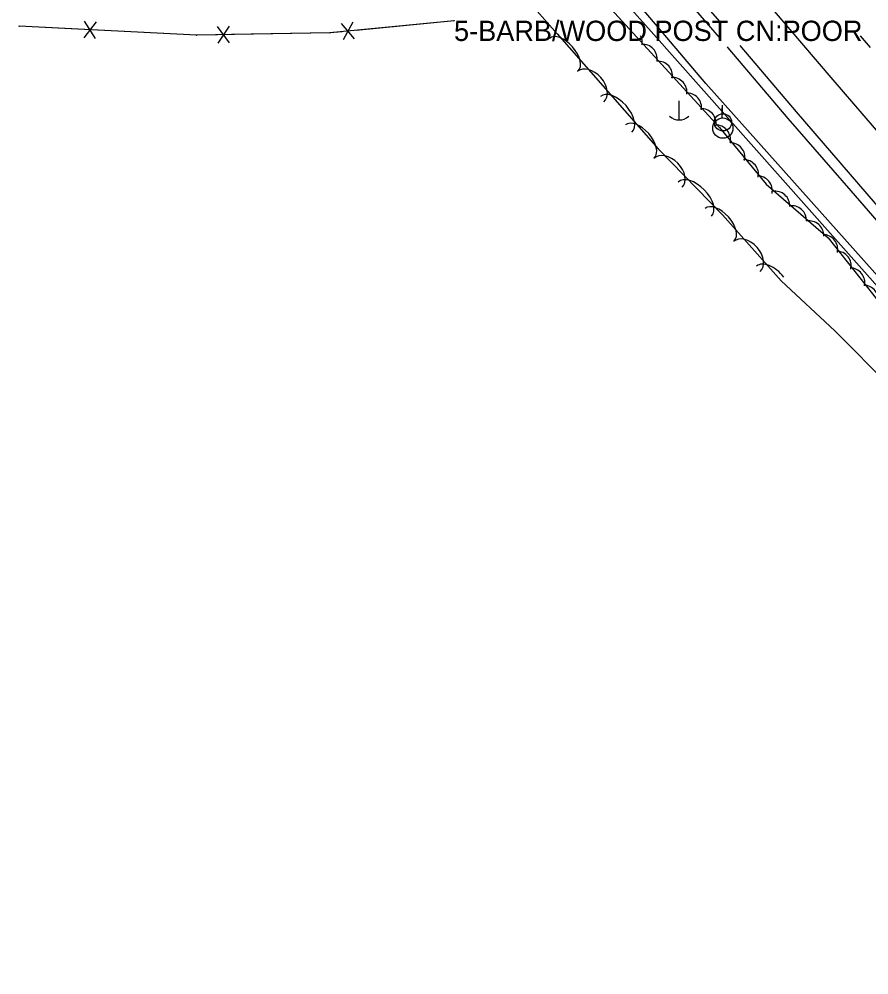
# Model space of a CAD drawing. Extents: x 954793 to 988390, y 1867850 to 1924428.
# Drawn here: x 965332 to 965541.5, y 1898519 to 1898754.5 of the extents above; entities that cross this region are included whole.
import ezdxf

# ---------------------------------------------------------------- set-up
doc = ezdxf.new("R2010")
doc.units = 0
for name, color, linetype in [('S_DITCHLINE', 7, 'Continuous'), ('S_EDGE_PAVEMENT', 7, 'Continuous'), ('S_FENCE', 7, 'Continuous'), ('S_FENCE_ANNOT', 7, 'Continuous'), ('S_MSC_PT_SYM', 7, 'Continuous'), ('S_PAVEMENT_CROWN', 7, 'Continuous'), ('S_SHOULDER', 7, 'Continuous'), ('S_TREE', 7, 'Continuous'), ('S_UTILITY_POLE', 7, 'Continuous')]:
    doc.layers.add(name, color=color, linetype=linetype)

msp = doc.modelspace()

# ---------------------------------------------------------------- linework, layer by layer
at = {"layer": 'S_DITCHLINE'}
for points in [[(965553.26, 1898680.48), (965540.28, 1898695.02), (965527.3, 1898709.56), (965514.32, 1898724.1), (965501.34, 1898738.65), (965489.36, 1898752.73), (965477.38, 1898766.82)], [(965552.07, 1898679.14), (965539.1, 1898693.76), (965526.12, 1898708.39), (965513.15, 1898723.02), (965500.18, 1898737.65), (965487.84, 1898751.51), (965475.51, 1898765.38)]]:
    msp.add_lwpolyline(points, dxfattribs=at)
at = {"layer": 'S_EDGE_PAVEMENT'}
for points in [[(965504.83, 1898753.86), (965499.61, 1898759.99)], [(965541.89, 1898747.52), (965539.42, 1898750.42)], [(965554.4, 1898696.05), (965539.02, 1898713.89), (965523.65, 1898731.73), (965509.77, 1898748.04)]]:
    msp.add_lwpolyline(points, dxfattribs=at)
at = {"layer": 'S_FENCE'}
for p, q in [((965375.73, 1898750.6), (965332.09, 1898752.81)), ((965351.04, 1898753.9), (965347.97, 1898749.95)), ((965350.83, 1898749.81), (965348.17, 1898754.04)), ((965383.86, 1898748.68), (965380.92, 1898752.73)), ((965383.79, 1898752.78), (965380.99, 1898748.63)), ((965439.24, 1898754.16), (965408.64, 1898751.14)), ((965414.74, 1898749.69), (965411.48, 1898753.48)), ((965414.34, 1898753.76), (965411.88, 1898749.41)), ((965408.64, 1898751.14), (965375.73, 1898750.6))]:
    msp.add_line(p, q, dxfattribs=at)
for points in [[(965348.07, 1898752), (965332.09, 1898752.81)], [(965439.24, 1898754.16), (965415.1, 1898751.78)], [(965375.73, 1898750.6), (965351.5, 1898751.82)], [(965380.96, 1898750.68), (965375.73, 1898750.6)], [(965408.64, 1898751.14), (965384.39, 1898750.74)], [(965411.68, 1898751.44), (965408.64, 1898751.14)]]:
    msp.add_lwpolyline(points, dxfattribs=at)
at = {"layer": 'S_MSC_PT_SYM'}
for points in [[(965332.09, 1898752.81), (965332.09, 1898752.86), (965332.09, 1898752.81), (965332.04, 1898752.81), (965332.09, 1898752.81), (965332.09, 1898752.76), (965332.09, 1898752.81), (965332.14, 1898752.81)], [(965439.24, 1898754.16), (965439.24, 1898754.21), (965439.24, 1898754.16), (965439.19, 1898754.16), (965439.24, 1898754.16), (965439.24, 1898754.11), (965439.24, 1898754.16), (965439.29, 1898754.16)], [(965375.73, 1898750.6), (965375.73, 1898750.65), (965375.73, 1898750.6), (965375.68, 1898750.6), (965375.73, 1898750.6), (965375.73, 1898750.55), (965375.73, 1898750.6), (965375.78, 1898750.6)], [(965408.64, 1898751.14), (965408.64, 1898751.19), (965408.64, 1898751.14), (965408.59, 1898751.14), (965408.64, 1898751.14), (965408.64, 1898751.09), (965408.64, 1898751.14), (965408.69, 1898751.14)]]:
    msp.add_lwpolyline(points, dxfattribs=at)
at = {"layer": 'S_PAVEMENT_CROWN'}
msp.add_lwpolyline([(965548.02, 1898721.84), (965532.67, 1898739.61), (965517.73, 1898757.07)], dxfattribs=at)
at = {"layer": 'S_SHOULDER'}
for points in [[(965504.65, 1898750.01), (965496.23, 1898759.91)], [(965552.61, 1898694.39), (965537.13, 1898712.22), (965521.64, 1898730.04), (965506.79, 1898747.5), (965506.63, 1898747.68)]]:
    msp.add_lwpolyline(points, dxfattribs=at)
at = {"layer": 'S_TREE'}
for points in [[(965453.09, 1898784.3), (965504.67, 1898727.83), (965516.2, 1898713.86), (965531.44, 1898700.64), (965542.41, 1898686.8), (965552.92, 1898673.25), (965559.36, 1898665.6), (965567.34, 1898658.17)], [(965444.39, 1898774), (965464.64, 1898750.89), (965489.53, 1898722.55), (965505.39, 1898706.31), (965519.91, 1898690.06), (965533.08, 1898677.75), (965546.83, 1898663.95), (965562.76, 1898644.46), (965589.91, 1898611.83), (965644.93, 1898544.22), (965653.51, 1898534.01), (965665.49, 1898518.97)]]:
    msp.add_lwpolyline(points, dxfattribs=at)
for centre, start, end in [((965482.01, 1898748.75), 351.6107, 28.01), ((965485.68, 1898744.73), 351.6107, 93.2076), ((965489.47, 1898740.54), 351.6107, 93.2076), ((965493.01, 1898736.55), 351.6107, 93.2076), ((965496.63, 1898732.7), 351.6107, 93.2076), ((965500.23, 1898728.81), 351.6107, 93.2076), ((965503.75, 1898724.83), 348.7376, 90.3345), ((965507.31, 1898720.45), 348.7376, 90.3345), ((965510.65, 1898716.29), 348.7376, 90.3345), ((965514.07, 1898712.26), 348.7376, 90.3345), ((965518.39, 1898708.48), 358.2319, 99.8288), ((965522.5, 1898704.91), 358.2319, 99.8288), ((965526.74, 1898701.19), 358.2319, 99.8288), ((965530.18, 1898697.82), 347.6183, 89.2152), ((965533.52, 1898693.72), 347.6183, 89.2152), ((965536.85, 1898689.59), 347.6183, 89.2152), ((965540.23, 1898685.32), 347.6183, 89.2152)]:
    msp.add_arc(centre, 3.64, start, end, dxfattribs=at)
for centre, major_axis, ratio, start_param in [((965466.29, 1898745.79), (-3.53, 4.02), 0.540699, 3.141593), ((965472.9, 1898737.88), (-3.27, 3.72), 0.68531, 3.141593), ((965479.21, 1898731.09), (-3.87, 4.41), 0.550079, 3.141593), ((965485.06, 1898724.43), (-3.53, 4.02), 0.540699, 3.141593), ((965491.98, 1898716.64), (-3.46, 3.55), 0.68531, 3.141593), ((965498.63, 1898710.19), (-4.1, 4.2), 0.550079, 3.141593), ((965504.72, 1898703.88), (-3.56, 3.99), 0.540699, 3.141593), ((965511.39, 1898696.02), (-3.3, 3.7), 0.68531, 3.141593), ((965517.75, 1898689.29), (-3.91, 4.38), 0.550079, 4.605083)]:
    msp.add_ellipse(centre, major_axis=major_axis, ratio=ratio, start_param=start_param, end_param=6.283185, dxfattribs=at)
at = {"layer": 'S_UTILITY_POLE'}
for p, q in [((965494.66, 1898734.41), (965494.66, 1898729.68)), ((965505.36, 1898730.21), (965505.36, 1898732.69)), ((965505.41, 1898731.25), (965505.41, 1898733.36))]:
    msp.add_line(p, q, dxfattribs=at)
for centre, radius in [((965505.53, 1898729.11), 2.13), ((965505.5, 1898727.69), 2.5)]:
    msp.add_circle(centre, radius, dxfattribs=at)
msp.add_arc((965494.73, 1898733.1), 3.41, 226.3972, 313.6028, dxfattribs=at)

# ---------------------------------------------------------------- texts
at = {"layer": 'S_FENCE_ANNOT'}
msp.add_text('5-BARB/WOOD POST CN:POOR', height=5, dxfattribs=at).set_placement((965439.24, 1898749.16))

doc.saveas('drawing.dxf')
